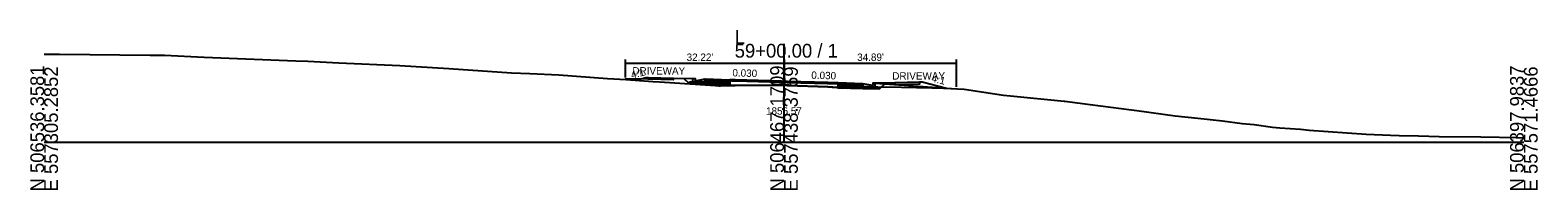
# Model space of a CAD drawing. Extents: x -26 to 4603, y -10 to 4703.
# Drawn here: x 1997.2 to 2302.8, y 4085.3 to 4117.8 of the extents above; entities that cross this region are included whole.
import ezdxf

# ---------------------------------------------------------------- set-up
doc = ezdxf.new("R2010")
doc.units = 0
for name, color, linetype in [('Default', 7, 'Continuous'), ('Exist Cross Section Cell', 7, 'Continuous'), ('Exist XS Ground Line', 7, 'Continuous'), ('Prop CMT Pvmt Course 1', 7, 'Continuous'), ('Prop CMT Pvmt Course 2', 7, 'Continuous'), ('Prop CMT Pvmt Course 3', 7, 'Continuous'), ('Prop CMT Pvmt Milling', 7, 'Continuous'), ('Prop CMT Shear Line', 7, 'Continuous'), ('Prop CMT Shld Paved Course 2', 7, 'Continuous'), ('Prop CMT Shld Paved Course 3', 7, 'Continuous'), ('Prop CMT Subgrade Earthwork', 7, 'Continuous'), ('Prop Conc Curb and Gutter', 7, 'Continuous'), ('Prop Corridor Mesh Bottom', 7, 'Continuous'), ('Prop XS Finish Grade', 7, 'Continuous'), ('Prop XS Label Text', 7, 'Continuous'), ('Prop XS SS Elevation Text', 7, 'Continuous'), ('Scratch_Level_0', 7, 'Continuous'), ('Scratch_Level_9', 7, 'Continuous')]:
    doc.layers.add(name, color=color, linetype=linetype)

msp = doc.modelspace()

# ---------------------------------------------------------------- linework, layer by layer
at = {"layer": 'Exist Cross Section Cell'}
for p, q in [((2150, 4095), (2150, 4115)), ((2000, 4095), (2150, 4095)), ((2150, 4095), (2300, 4095))]:
    msp.add_line(p, q, dxfattribs=at)
at = {"layer": 'Exist XS Ground Line'}
msp.add_lwpolyline([(2000, 4112.91), (2003.09, 4112.88), (2021.49, 4112.7), (2022.94, 4112.69), (2024.41, 4112.68), (2032.46, 4112.32), (2051.01, 4111.56), (2053.49, 4111.46), (2059.71, 4111.12), (2072.1, 4110.61), (2082.07, 4109.99), (2094.77, 4109.14), (2098.45, 4108.96), (2104.32, 4108.67), (2114.21, 4107.99), (2118.02, 4107.78), (2123.4, 4107.38), (2124.79, 4107.26), (2136.11, 4106.54), (2136.82, 4106.47), (2137.12, 4106.44), (2137.13, 4106.45), (2139.41, 4106.51), (2139.53, 4106.51), (2140.07, 4106.52), (2149.47, 4106.59), (2150.74, 4106.54), (2158.89, 4106.25), (2161.62, 4106.08), (2162.91, 4106.02), (2162.99, 4106.1), (2163.01, 4106.12), (2163.85, 4106.12), (2166.9, 4106.1), (2166.95, 4106.11), (2167.14, 4106.12), (2167.52, 4106.13), (2170.71, 4106.23), (2180, 4106.06), (2180.88, 4106.05), (2183.8, 4105.91), (2186.54, 4105.76), (2194.52, 4104.57), (2195.92, 4104.43), (2206.77, 4103.36), (2206.93, 4103.34), (2212.1, 4102.7), (2220.48, 4101.58), (2221.55, 4101.46), (2229.31, 4100.4), (2233.88, 4099.91), (2238.91, 4099.36), (2242.9, 4098.8), (2245.31, 4098.61), (2249.05, 4098.07), (2250.5, 4097.94), (2254.74, 4097.67), (2256.45, 4097.45), (2268.01, 4096.65), (2272.98, 4096.41), (2274.73, 4096.35), (2278.64, 4096.28), (2282.85, 4096.2), (2291.25, 4096.13), (2298.81, 4095.94), (2300, 4095.91)], dxfattribs=at)
at = {"layer": 'Prop CMT Pvmt Course 1'}
for points in [[(2134, 4107.86), (2139, 4107.71), (2139, 4107.71), (2139, 4107.46), (2134, 4107.61), (2134, 4107.61), (2134, 4107.86), (2134, 4107.86), (2134, 4107.86)], [(2149.47, 4107.39), (2149.47, 4107.39), (2140.07, 4107.67), (2140.07, 4107.67), (2139.53, 4107.69), (2139.41, 4107.69), (2139.41, 4107.69), (2139, 4107.71), (2139, 4107.71), (2139, 4107.71), (2139, 4106.5), (2139, 4106.5), (2139.41, 4106.51), (2139.41, 4106.51), (2139.53, 4106.51), (2140.07, 4106.52), (2140.07, 4106.52), (2149.47, 4106.59), (2149.47, 4106.59), (2149.47, 4106.59), (2150, 4106.57), (2150, 4107.38), (2150, 4107.38), (2149.47, 4107.39), (2149.47, 4107.39)], [(2158.89, 4107.11), (2158.89, 4107.11), (2150.74, 4107.35), (2150.74, 4107.35), (2150, 4107.38), (2150, 4107.38), (2150, 4106.57), (2150.74, 4106.54), (2150.74, 4106.54), (2158.89, 4106.25), (2158.89, 4106.25), (2158.89, 4106.25), (2161, 4106.12), (2161, 4107.05), (2161, 4107.05), (2158.89, 4107.11), (2158.89, 4107.11)], [(2161, 4107.05), (2161, 4107.05), (2161, 4107.05), (2161, 4106.8), (2161, 4106.8), (2166, 4106.65), (2166, 4106.9), (2166, 4106.9), (2161, 4107.05)]]:
    msp.add_lwpolyline(points, dxfattribs=at)
at = {"layer": 'Prop CMT Pvmt Course 2'}
for points in [[(2134, 4107.61), (2139, 4107.46), (2139, 4107.46), (2139, 4107.12), (2134, 4107.27), (2134, 4107.27), (2134, 4107.61), (2134, 4107.61), (2134, 4107.61)], [(2161, 4106.8), (2161, 4106.8), (2161, 4106.8), (2161, 4106.46), (2161, 4106.46), (2166, 4106.31), (2166, 4106.65), (2166, 4106.65), (2161, 4106.8)]]:
    msp.add_lwpolyline(points, dxfattribs=at)
at = {"layer": 'Prop CMT Pvmt Course 3'}
for points in [[(2134, 4107.27), (2139, 4107.12), (2139, 4107.12), (2139, 4106.75), (2134, 4106.9), (2134, 4106.9), (2134, 4107.27), (2134, 4107.27), (2134, 4107.27)], [(2161, 4106.46), (2161, 4106.46), (2161, 4106.46), (2161, 4106.09), (2161, 4106.09), (2166, 4105.94), (2166, 4106.31), (2166, 4106.31), (2161, 4106.46)], [(2166, 4106.31), (2166, 4106.31), (2166, 4106.31), (2166, 4105.94), (2166, 4105.94), (2169.39, 4105.84), (2169, 4106.22), (2169, 4106.22), (2166, 4106.31)]]:
    msp.add_lwpolyline(points, dxfattribs=at)
at = {"layer": 'Prop CMT Pvmt Milling'}
for points in [[(2150, 4106.57), (2149.47, 4106.59), (2149.47, 4106.59), (2149.47, 4106.59), (2140.07, 4106.52), (2140.07, 4106.52), (2139.53, 4106.51), (2139.41, 4106.51), (2139.41, 4106.51), (2139, 4106.5), (2139, 4106.5)], [(2161, 4106.12), (2158.89, 4106.25), (2158.89, 4106.25), (2158.89, 4106.25), (2150.74, 4106.54), (2150.74, 4106.54), (2150, 4106.57)]]:
    msp.add_lwpolyline(points, dxfattribs=at)
at = {"layer": 'Prop CMT Shld Paved Course 2'}
for points in [[(2149.47, 4107.14), (2149.47, 4107.14), (2140.07, 4107.42), (2140.07, 4107.42), (2139.53, 4107.44), (2139.41, 4107.44), (2139.41, 4107.44), (2139, 4107.46), (2139, 4107.46), (2139, 4107.46), (2139, 4106.5), (2139, 4106.5), (2139.41, 4106.51), (2139.41, 4106.51), (2139.53, 4106.51), (2140.07, 4106.52), (2140.07, 4106.52), (2149.47, 4106.59), (2149.47, 4106.59), (2149.47, 4106.59), (2150, 4106.57), (2150, 4107.13), (2150, 4107.13), (2149.47, 4107.14), (2149.47, 4107.14)], [(2158.89, 4106.86), (2158.89, 4106.86), (2150.74, 4107.1), (2150.74, 4107.1), (2150, 4107.13), (2150, 4107.13), (2150, 4106.57), (2150.74, 4106.54), (2150.74, 4106.54), (2158.89, 4106.25), (2158.89, 4106.25), (2158.89, 4106.25), (2161, 4106.12), (2161, 4106.8), (2161, 4106.8), (2158.89, 4106.86), (2158.89, 4106.86)]]:
    msp.add_lwpolyline(points, dxfattribs=at)
at = {"layer": 'Prop CMT Shld Paved Course 3'}
msp.add_lwpolyline([(2131, 4107.36), (2134, 4107.27), (2134, 4107.27), (2134, 4106.9), (2130.7, 4107), (2130.7, 4107), (2131, 4107.36), (2131, 4107.36), (2131, 4107.36)], dxfattribs=at)
at = {"layer": 'Prop CMT Subgrade Earthwork'}
for points in [[(2130.7, 4107), (2130.7, 4107), (2139, 4106.75)], [(2169.39, 4105.84), (2161, 4106.09), (2161, 4106.09)], [(2170.41, 4106.86), (2169.39, 4105.84)]]:
    msp.add_lwpolyline(points, dxfattribs=at)
at = {"layer": 'Prop Conc Curb and Gutter'}
for points in [[(2134, 4107.86), (2134, 4107.86), (2134, 4107.86), (2134, 4107.27), (2131.5, 4107.35), (2131.5, 4107.35), (2131.5, 4107.96), (2131.5, 4107.96), (2132, 4107.96), (2132, 4107.96), (2132, 4107.96), (2132, 4107.46), (2134, 4107.86)], [(2166, 4106.9), (2166, 4106.9), (2166, 4106.9), (2166, 4106.31), (2166, 4106.31), (2168.5, 4106.24), (2168.5, 4107), (2168.5, 4107), (2168, 4107), (2168, 4107), (2168, 4107), (2168, 4106.5), (2166, 4106.9)]]:
    msp.add_lwpolyline(points, dxfattribs=at)
at = {"layer": 'Prop Corridor Mesh Bottom'}
msp.add_lwpolyline([(2166, 4106.9), (2166, 4106.65)], dxfattribs=at)
at = {"layer": 'Prop XS Finish Grade'}
for p, q in [((2131.5, 4107.96), (2117.78, 4107.79)), ((2168.5, 4107), (2184.89, 4105.85))]:
    msp.add_line(p, q, dxfattribs=at)
at = {"layer": 'Prop XS Label Text'}
for p, q in [((2117.78, 4111.82), (2117.78, 4108.19)), ((2150, 4111.82), (2150, 4107.93)), ((2184.89, 4111.82), (2184.89, 4106.28)), ((2184.89, 4111.03), (2117.78, 4111.03))]:
    msp.add_line(p, q, dxfattribs=at)
at = {"layer": 'Scratch_Level_0'}
for points in [[(2119.97, 4107.64), (2122, 4108.15), (2122, 4108.15)], [(2122, 4108.15), (2122, 4108.15), (2122.5, 4108.14)], [(2122.5, 4108.14), (2127.5, 4108.04), (2127.5, 4108.04), (2127.51, 4107.7), (2122.49, 4107.8), (2122.49, 4107.8), (2122.5, 4108.14), (2122.5, 4108.14), (2122.5, 4108.14)], [(2127.5, 4108.04), (2127.5, 4108.04), (2131.5, 4107.96)], [(2129.71, 4107.99), (2129.71, 4107.99), (2130.7, 4107)], [(2172.5, 4107.08), (2172.5, 4107.08), (2168.5, 4107)], [(2177.5, 4107.18), (2172.5, 4107.08), (2172.5, 4107.08), (2172.49, 4106.74), (2177.51, 4106.84), (2177.51, 4106.84), (2177.5, 4107.18), (2177.5, 4107.18), (2177.5, 4107.18)], [(2178, 4107.19), (2178, 4107.19), (2177.5, 4107.18)], [(2182.94, 4105.95), (2178, 4107.19), (2178, 4107.19)]]:
    msp.add_lwpolyline(points, dxfattribs=at)
at = {"layer": 'Scratch_Level_9'}
msp.add_lwpolyline([(2134, 4107.86), (2134, 4107.61)], dxfattribs=at)

# ---------------------------------------------------------------- texts
at = {"layer": 'Default'}
msp.add_text('-', height=0.0001, dxfattribs=at).set_placement((2000, 4095))
at = {"layer": 'Exist Cross Section Cell'}
for s, p in [('L', (2140, 4115)), ('59+00.00 / 1', (2140, 4112.2))]:
    msp.add_text(s, height=2.8, dxfattribs=at).set_placement(p)
for s, p in [('N 506536.3581', (2000, 4085)), ('E 557305.2852', (2002.8, 4085)), ('N 506467.1709', (2150, 4085)), ('E 557438.3759', (2152.8, 4085)), ('N 506397.9837', (2300, 4085)), ('E 557571.4666', (2302.8, 4085))]:
    msp.add_text(s, height=2.8, rotation=90, dxfattribs=at).set_placement(p)
at = {"layer": 'Prop CMT Shear Line'}
for p in [(2132, 4107.45), (2134, 4107.85), (2134, 4107.85), (2150, 4107.37), (2166, 4106.89), (2166, 4106.89), (2168, 4106.49), (2182.94, 4105.95)]:
    msp.add_text('X', height=0.0025, dxfattribs=at).set_placement(p)
at = {"layer": 'Prop XS Label Text'}
for s, rotation, p in [("32.22'", 0.0969, (2130.26, 4111.53)), ("34.89'", 0.0969, (2164.84, 4111.53)), ('DRIVEWAY', 359.9031, (2119.26, 4108.77)), ('0.030', 358.2816, (2139.52, 4108.39)), ('0.030', 358.2816, (2155.52, 4107.91)), ('DRIVEWAY', 0.0969, (2171.95, 4107.73))]:
    msp.add_text(s, height=1.5, rotation=rotation, dxfattribs=at).set_placement(p)
at = {"layer": 'Prop XS SS Elevation Text'}
msp.add_text('1856.57', height=1.5, dxfattribs=at).set_placement((2146.36, 4100.6))
at = {"layer": 'Scratch_Level_0'}
for rotation, p in [(14.0362, (2119.15, 4107.92)), (345.9638, (2179.8, 4107.34))]:
    msp.add_text('4:1', height=1.5, rotation=rotation, dxfattribs=at).set_placement(p)
for p in [(2119.97, 4107.64), (2122, 4108.14), (2122.5, 4108.13), (2127.5, 4108.03), (2172.5, 4107.07), (2177.5, 4107.17), (2178, 4107.18)]:
    msp.add_text('X', height=0.0025, dxfattribs=at).set_placement(p)

doc.saveas('drawing.dxf')
